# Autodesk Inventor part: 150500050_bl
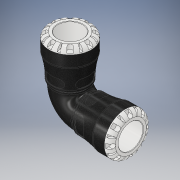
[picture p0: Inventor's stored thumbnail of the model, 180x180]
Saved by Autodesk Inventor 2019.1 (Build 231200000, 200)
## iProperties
Created: 2016-12
Part Number: 150500050_bl
Material: PVC-Piping
Description: PLASSON G-PLASS 90°  ELBOW 50X50
Document SubType Name: Modeling
Designer: KIM
Mass: 664.223 g
Surface Area: 733.008 cm^2
Volume: 474.445 cm^3
Density: 1.4 g/cm^3
Appearance: Black Cast
Author: KIM
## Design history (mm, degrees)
derived "150500.ipt"
feature "Solid1::150500.ipt" dims "ScaleForDerivedMember" = 10
tag "TaggingFeature1"
body "Solid1"
other parameters: "d1" = 34.86 [user parameter], "d3" = 62.5 [user parameter], "d4" = 85 [user parameter], "d8" = 72.25 [user parameter], "d13" = 9 [user parameter], "d14" = 9 [user parameter], "d15" = 0 [user parameter], "d17" = 360 deg [user parameter], "d19" = 8 deg [user parameter], "d20" = 1 [user parameter], "d21" = 1 [user parameter], "d22" = 8 deg [user parameter], "d24" = 0 [user parameter], "d26" = 360 deg [user parameter], "d33" = 8.5 [user parameter], "d43" = 66.3 [user parameter], "d51" = 0.85 [user parameter], "d54" = 17.5 [user parameter], "d55" = 11 [user parameter], "d57" = 17.64 [user parameter], "d58" = 0 [user parameter], "d74" = 0 [user parameter], "d77" = 4.16667 [user parameter], "d78" = 83 [user parameter], "d82" = 1 [user parameter], "d115" = 360 deg [user parameter], "d207" = 90 deg [user parameter], "d228" = 14.875 [user parameter], "d247" = 1.7 [user parameter], "d248" = 4.98 [user parameter], "d268" = 39.7375 [user parameter], "d269" = 4.98 [user parameter], "d270" = 123 [user parameter], "d272" = 90 deg [user parameter], "d274" = 0 [user parameter], "d275" = 0 [user parameter], "E_" = 85 [user parameter], "l_" = 83 [user parameter], "A_" = 123 [user parameter], "d9" = 11.25 [user parameter], "d11" = 85 [user parameter], "d12" = 62.5 [user parameter]
